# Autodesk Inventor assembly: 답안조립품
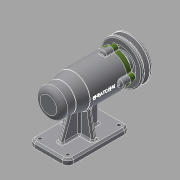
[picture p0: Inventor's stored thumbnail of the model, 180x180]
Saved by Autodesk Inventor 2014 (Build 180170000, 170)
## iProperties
Created: 2019-07
Part Number: 답안조립품
Document SubType Name: Assembly
Designer: kb542-17
Author: kb542-17
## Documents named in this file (12)
- C:\Users\kb542-17\Desktop\490704V1058\답안조립품.iam
- C:\Users\kb542-17\Desktop\490704V1058\본체.ipt
- C:\Users\kb542-17\Desktop\490704V1058\축.ipt
- C:\Users\kb542-17\Desktop\490704V1058\베어링 6004.ipt
- C:\Users\kb542-17\Desktop\490704V1058\어댑터슬리브.ipt
- C:\Users\kb542-17\Desktop\490704V1058\베어링 51202.ipt
- C:\Users\kb542-17\Desktop\490704V1058\볼트 M4.ipt
- C:\Users\kb542-17\Desktop\490704V1058\커버.ipt
- C:\Users\kb542-17\Desktop\490704V1058\오일 실.ipt
- C:\Users\kb542-17\Desktop\490704V1058\V벨트풀리.ipt
- C:\Users\kb542-17\Desktop\490704V1058\키 5 x 5 x 16.ipt
- C:\Users\kb542-17\Desktop\490704V1058\멈춤나사 M3.ipt
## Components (1 placed, 1 different names)
1. V벨트풀리:1
